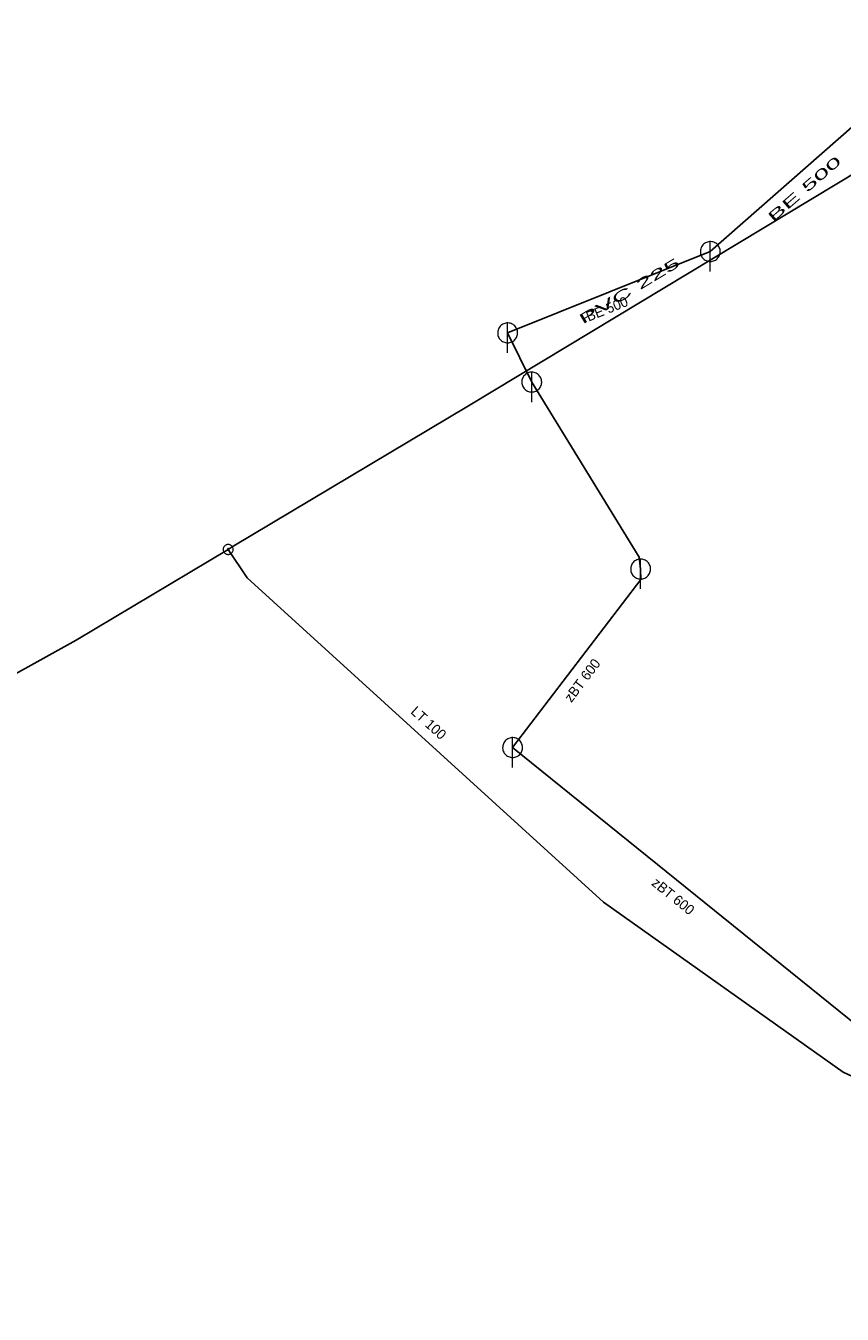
# Model space of a CAD drawing. Extents: x -659250 to -657316, y -997555 to -993684.
# Drawn here: x -658279.6 to -658197.6, y -995124.1 to -994994.7 of the extents above; entities that cross this region are included whole.
import ezdxf

# ---------------------------------------------------------------- set-up
doc = ezdxf.new("R2010")
doc.units = 0
doc.header["$LTSCALE"] = 0.4
doc.layers.add('1', color=7, linetype='Continuous')
for name, color, linetype, lineweight in [('14', 7, 'Continuous', 25), ('17', 7, 'Continuous', 25), ('22', 7, 'Continuous', 13), ('47', 7, 'Continuous', 13)]:
    doc.layers.add(name, color=color, linetype=linetype, lineweight=lineweight)

msp = doc.modelspace()

# ---------------------------------------------------------------- linework, layer by layer
at = {"layer": '14'}
for p, q in [((-658196.329, -995004.66), (-658210.829, -995017.39)), ((-658210.829, -995017.39), (-658231.19, -995025.559)), ((-658231.19, -995025.559), (-658228.766, -995030.5)), ((-658230.69, -995067.21), (-658194.982, -995096.022))]:
    msp.add_line(p, q, dxfattribs=at)
for points in [[(-658228.766, -995030.5), (-658217.959, -995048.091), (-658217.827, -995049.282)], [(-658217.827, -995049.282), (-658217.803, -995050.324), (-658230.69, -995067.21)]]:
    msp.add_lwpolyline(points, dxfattribs=at)
at = {"layer": '17'}
for points in [[(-658170.41, -994994.71), (-658180.989, -995000.263), (-658235.118, -995032.881), (-658258.852, -995047.041), (-658259.263, -995047.311)], [(-658259.263, -995047.311), (-658274.545, -995056.438), (-658315.531, -995079.142), (-658388.274, -995112.102), (-658418.381, -995115.664), (-658425.669, -995116.129), (-658489.359, -995122.5)], [(-658062.373, -995124.127), (-658085.166, -995121.715), (-658104.599, -995119.601), (-658136.438, -995115.484), (-658174.067, -995110.673), (-658197.491, -995099.798), (-658221.556, -995082.743), (-658257.348, -995050.168), (-658259.263, -995047.311)]]:
    msp.add_lwpolyline(points, dxfattribs=at)
at = {"layer": '22'}
for p, q in [((-658210.829, -995019.39), (-658210.828, -995016.39)), ((-658231.19, -995027.559), (-658231.189, -995024.559)), ((-658228.766, -995032.5), (-658228.765, -995029.5)), ((-658217.827, -995051.282), (-658217.826, -995048.282)), ((-658230.69, -995069.21), (-658230.689, -995066.21))]:
    msp.add_line(p, q, dxfattribs=at)
for points in [[(-658209.829, -995017.39), (-658209.834, -995017.281), (-658209.852, -995017.173), (-658209.882, -995017.067), (-658209.922, -995016.966), (-658209.974, -995016.869), (-658210.036, -995016.779), (-658210.108, -995016.696), (-658210.188, -995016.622), (-658210.276, -995016.556), (-658210.37, -995016.501), (-658210.47, -995016.456), (-658210.575, -995016.423), (-658210.682, -995016.401), (-658210.791, -995016.391), (-658210.901, -995016.393), (-658211.009, -995016.407), (-658211.116, -995016.432), (-658211.219, -995016.469), (-658211.317, -995016.518), (-658211.409, -995016.576), (-658211.495, -995016.645), (-658211.572, -995016.722), (-658211.641, -995016.808), (-658211.7, -995016.9), (-658211.748, -995016.998), (-658211.785, -995017.101), (-658211.811, -995017.208), (-658211.825, -995017.316), (-658211.828, -995017.426), (-658211.818, -995017.535), (-658211.797, -995017.642), (-658211.763, -995017.746), (-658211.719, -995017.846), (-658211.664, -995017.941), (-658211.598, -995018.029), (-658211.524, -995018.109), (-658211.441, -995018.181), (-658211.351, -995018.243), (-658211.255, -995018.295), (-658211.153, -995018.336), (-658211.048, -995018.366), (-658210.94, -995018.384), (-658210.83, -995018.39), (-658210.721, -995018.384), (-658210.613, -995018.366), (-658210.508, -995018.337), (-658210.406, -995018.296), (-658210.309, -995018.244), (-658210.219, -995018.182), (-658210.136, -995018.111), (-658210.061, -995018.031), (-658209.996, -995017.943), (-658209.94, -995017.849), (-658209.896, -995017.749), (-658209.862, -995017.645), (-658209.84, -995017.537), (-658209.83, -995017.428)], [(-658230.19, -995025.559), (-658230.195, -995025.45), (-658230.213, -995025.342), (-658230.243, -995025.236), (-658230.283, -995025.135), (-658230.335, -995025.038), (-658230.397, -995024.948), (-658230.469, -995024.865), (-658230.549, -995024.791), (-658230.637, -995024.725), (-658230.731, -995024.67), (-658230.831, -995024.625), (-658230.936, -995024.592), (-658231.043, -995024.57), (-658231.152, -995024.56), (-658231.262, -995024.562), (-658231.37, -995024.576), (-658231.477, -995024.601), (-658231.58, -995024.638), (-658231.678, -995024.687), (-658231.77, -995024.745), (-658231.856, -995024.814), (-658231.933, -995024.891), (-658232.002, -995024.977), (-658232.061, -995025.069), (-658232.109, -995025.167), (-658232.146, -995025.27), (-658232.172, -995025.377), (-658232.186, -995025.485), (-658232.189, -995025.595), (-658232.179, -995025.704), (-658232.158, -995025.811), (-658232.124, -995025.915), (-658232.08, -995026.015), (-658232.025, -995026.11), (-658231.959, -995026.198), (-658231.885, -995026.278), (-658231.802, -995026.35), (-658231.712, -995026.412), (-658231.616, -995026.464), (-658231.514, -995026.505), (-658231.409, -995026.535), (-658231.301, -995026.553), (-658231.191, -995026.559), (-658231.082, -995026.553), (-658230.974, -995026.535), (-658230.869, -995026.506), (-658230.767, -995026.465), (-658230.67, -995026.413), (-658230.58, -995026.351), (-658230.497, -995026.28), (-658230.422, -995026.2), (-658230.357, -995026.112), (-658230.301, -995026.018), (-658230.257, -995025.918), (-658230.223, -995025.814), (-658230.201, -995025.706), (-658230.191, -995025.597)], [(-658227.766, -995030.5), (-658227.771, -995030.391), (-658227.789, -995030.283), (-658227.819, -995030.177), (-658227.859, -995030.076), (-658227.911, -995029.979), (-658227.973, -995029.889), (-658228.045, -995029.806), (-658228.125, -995029.732), (-658228.213, -995029.666), (-658228.307, -995029.611), (-658228.407, -995029.566), (-658228.512, -995029.533), (-658228.619, -995029.511), (-658228.728, -995029.501), (-658228.838, -995029.503), (-658228.946, -995029.517), (-658229.053, -995029.542), (-658229.156, -995029.579), (-658229.254, -995029.628), (-658229.346, -995029.686), (-658229.432, -995029.755), (-658229.509, -995029.832), (-658229.578, -995029.918), (-658229.637, -995030.01), (-658229.685, -995030.108), (-658229.722, -995030.211), (-658229.748, -995030.318), (-658229.762, -995030.426), (-658229.765, -995030.536), (-658229.755, -995030.645), (-658229.734, -995030.752), (-658229.7, -995030.856), (-658229.656, -995030.956), (-658229.601, -995031.051), (-658229.535, -995031.139), (-658229.461, -995031.219), (-658229.378, -995031.291), (-658229.288, -995031.353), (-658229.192, -995031.405), (-658229.09, -995031.446), (-658228.985, -995031.476), (-658228.877, -995031.494), (-658228.767, -995031.5), (-658228.658, -995031.494), (-658228.55, -995031.476), (-658228.445, -995031.447), (-658228.343, -995031.406), (-658228.246, -995031.354), (-658228.156, -995031.292), (-658228.073, -995031.221), (-658227.998, -995031.141), (-658227.933, -995031.053), (-658227.877, -995030.959), (-658227.833, -995030.859), (-658227.799, -995030.755), (-658227.777, -995030.647), (-658227.767, -995030.538)], [(-658216.827, -995049.282), (-658216.832, -995049.173), (-658216.85, -995049.065), (-658216.88, -995048.959), (-658216.92, -995048.858), (-658216.972, -995048.761), (-658217.034, -995048.671), (-658217.106, -995048.588), (-658217.186, -995048.514), (-658217.274, -995048.448), (-658217.368, -995048.393), (-658217.468, -995048.348), (-658217.573, -995048.315), (-658217.68, -995048.293), (-658217.789, -995048.283), (-658217.899, -995048.285), (-658218.007, -995048.299), (-658218.114, -995048.324), (-658218.217, -995048.361), (-658218.315, -995048.41), (-658218.407, -995048.468), (-658218.493, -995048.537), (-658218.57, -995048.614), (-658218.639, -995048.7), (-658218.698, -995048.792), (-658218.746, -995048.89), (-658218.783, -995048.993), (-658218.809, -995049.1), (-658218.823, -995049.208), (-658218.826, -995049.318), (-658218.816, -995049.427), (-658218.795, -995049.534), (-658218.761, -995049.638), (-658218.717, -995049.738), (-658218.662, -995049.833), (-658218.596, -995049.921), (-658218.522, -995050.001), (-658218.439, -995050.073), (-658218.349, -995050.135), (-658218.253, -995050.187), (-658218.151, -995050.228), (-658218.046, -995050.258), (-658217.938, -995050.276), (-658217.828, -995050.282), (-658217.719, -995050.276), (-658217.611, -995050.258), (-658217.506, -995050.229), (-658217.404, -995050.188), (-658217.307, -995050.136), (-658217.217, -995050.074), (-658217.134, -995050.003), (-658217.059, -995049.923), (-658216.994, -995049.835), (-658216.938, -995049.741), (-658216.894, -995049.641), (-658216.86, -995049.537), (-658216.838, -995049.429), (-658216.828, -995049.32)], [(-658229.69, -995067.21), (-658229.695, -995067.101), (-658229.713, -995066.993), (-658229.743, -995066.887), (-658229.783, -995066.786), (-658229.835, -995066.689), (-658229.897, -995066.599), (-658229.969, -995066.516), (-658230.049, -995066.442), (-658230.137, -995066.376), (-658230.231, -995066.321), (-658230.331, -995066.276), (-658230.436, -995066.243), (-658230.543, -995066.221), (-658230.652, -995066.211), (-658230.762, -995066.213), (-658230.87, -995066.227), (-658230.977, -995066.252), (-658231.08, -995066.289), (-658231.178, -995066.338), (-658231.27, -995066.396), (-658231.356, -995066.465), (-658231.433, -995066.542), (-658231.502, -995066.628), (-658231.561, -995066.72), (-658231.609, -995066.818), (-658231.646, -995066.921), (-658231.672, -995067.028), (-658231.686, -995067.136), (-658231.689, -995067.246), (-658231.679, -995067.355), (-658231.658, -995067.462), (-658231.624, -995067.566), (-658231.58, -995067.666), (-658231.525, -995067.761), (-658231.459, -995067.849), (-658231.385, -995067.929), (-658231.302, -995068.001), (-658231.212, -995068.063), (-658231.116, -995068.115), (-658231.014, -995068.156), (-658230.909, -995068.186), (-658230.801, -995068.204), (-658230.691, -995068.21), (-658230.582, -995068.204), (-658230.474, -995068.186), (-658230.369, -995068.157), (-658230.267, -995068.116), (-658230.17, -995068.064), (-658230.08, -995068.002), (-658229.997, -995067.931), (-658229.922, -995067.851), (-658229.857, -995067.763), (-658229.801, -995067.669), (-658229.757, -995067.569), (-658229.723, -995067.465), (-658229.701, -995067.357), (-658229.691, -995067.248)]]:
    msp.add_lwpolyline(points, close=True, dxfattribs=at)
at = {"layer": '47'}
for points in [[(-658258.764, -995047.311), (-658258.767, -995047.259), (-658258.775, -995047.206), (-658258.789, -995047.157), (-658258.806, -995047.108), (-658258.831, -995047.061), (-658258.86, -995047.017), (-658258.892, -995046.977), (-658258.929, -995046.94), (-658258.97, -995046.907), (-658259.014, -995046.878), (-658259.061, -995046.853), (-658259.11, -995046.836), (-658259.159, -995046.822), (-658259.212, -995046.814), (-658259.264, -995046.811), (-658259.316, -995046.814), (-658259.368, -995046.822), (-658259.419, -995046.836), (-658259.467, -995046.853), (-658259.514, -995046.878), (-658259.558, -995046.907), (-658259.598, -995046.94), (-658259.636, -995046.977), (-658259.669, -995047.017), (-658259.696, -995047.061), (-658259.721, -995047.108), (-658259.74, -995047.157), (-658259.752, -995047.206), (-658259.761, -995047.259), (-658259.764, -995047.311), (-658259.761, -995047.363), (-658259.752, -995047.415), (-658259.74, -995047.466), (-658259.721, -995047.514), (-658259.696, -995047.561), (-658259.669, -995047.605), (-658259.636, -995047.646), (-658259.598, -995047.683), (-658259.558, -995047.716), (-658259.514, -995047.744), (-658259.467, -995047.768), (-658259.419, -995047.787), (-658259.368, -995047.799), (-658259.316, -995047.808), (-658259.264, -995047.811), (-658259.212, -995047.808), (-658259.159, -995047.799), (-658259.11, -995047.787), (-658259.061, -995047.768), (-658259.014, -995047.744), (-658258.97, -995047.716), (-658258.929, -995047.683), (-658258.892, -995047.646), (-658258.86, -995047.605), (-658258.831, -995047.561), (-658258.806, -995047.514), (-658258.789, -995047.466), (-658258.775, -995047.415), (-658258.767, -995047.363)], [(-658259.181, -995047.311), (-658259.181, -995047.302), (-658259.184, -995047.294), (-658259.186, -995047.286), (-658259.189, -995047.277), (-658259.193, -995047.27), (-658259.198, -995047.263), (-658259.203, -995047.255), (-658259.208, -995047.25), (-658259.216, -995047.245), (-658259.223, -995047.24), (-658259.23, -995047.236), (-658259.239, -995047.233), (-658259.247, -995047.231), (-658259.255, -995047.228), (-658259.264, -995047.228), (-658259.272, -995047.228), (-658259.281, -995047.231), (-658259.289, -995047.233), (-658259.297, -995047.236), (-658259.304, -995047.24), (-658259.311, -995047.245), (-658259.319, -995047.25), (-658259.325, -995047.255), (-658259.331, -995047.263), (-658259.335, -995047.27), (-658259.338, -995047.277), (-658259.342, -995047.286), (-658259.343, -995047.294), (-658259.346, -995047.302), (-658259.346, -995047.311), (-658259.346, -995047.32), (-658259.343, -995047.328), (-658259.342, -995047.336), (-658259.338, -995047.344), (-658259.335, -995047.352), (-658259.331, -995047.358), (-658259.325, -995047.366), (-658259.319, -995047.372), (-658259.311, -995047.378), (-658259.304, -995047.382), (-658259.297, -995047.386), (-658259.289, -995047.389), (-658259.281, -995047.391), (-658259.272, -995047.393), (-658259.264, -995047.393), (-658259.255, -995047.393), (-658259.247, -995047.391), (-658259.239, -995047.389), (-658259.23, -995047.386), (-658259.223, -995047.382), (-658259.216, -995047.378), (-658259.208, -995047.372), (-658259.203, -995047.366), (-658259.198, -995047.358), (-658259.193, -995047.352), (-658259.189, -995047.344), (-658259.186, -995047.336), (-658259.184, -995047.328), (-658259.181, -995047.32)]]:
    msp.add_lwpolyline(points, close=True, dxfattribs=at)

# ---------------------------------------------------------------- texts
at = {"layer": '1'}
for s, rotation, width, p in [('BE 500', 41, 2.1, (-658204.524, -995014.496)), ('PVC 225 ', 31, 2.15, (-658223.644, -995024.728))]:
    msp.add_text(s, height=1, rotation=rotation, dxfattribs=dict(at, width=width)).set_placement(p)
for s, rotation, p in [('BE 500', 22, (-658223.053, -995024.434)), ('zBT 600 ', 53, (-658224.79, -995062.753)), ('LT 100', 318, (-658241.007, -995063.707)), ('zBT 600 ', 321, (-658216.805, -995080.962))]:
    msp.add_text(s, height=1, rotation=rotation, dxfattribs=at).set_placement(p)

doc.saveas('drawing.dxf')
